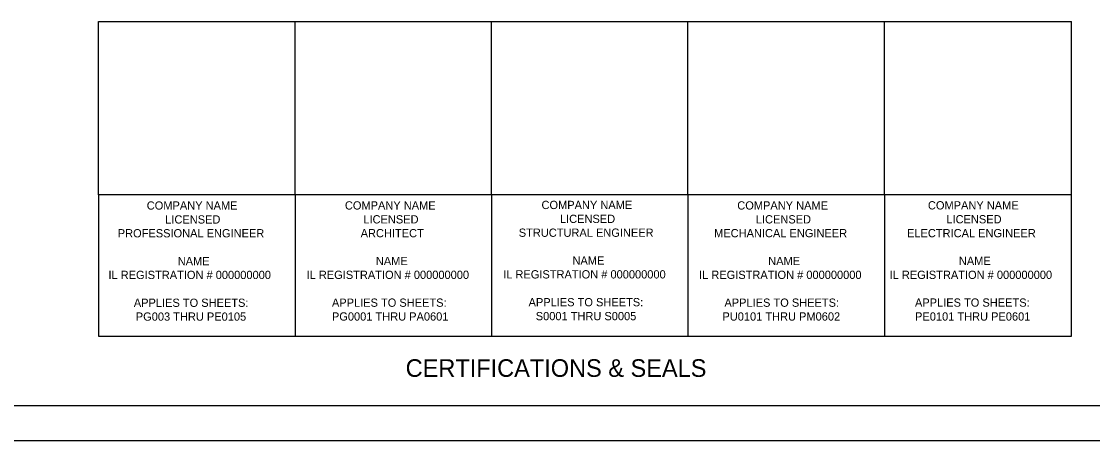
# Model space of a CAD drawing. Extents: x 46.6 to 90.4, y 0.3 to 22.3.
# Drawn here: x 58.96 to 70.28, y 0.26 to 4.69 of the extents above; entities that cross this region are included whole.
import ezdxf

# ---------------------------------------------------------------- set-up
doc = ezdxf.new("R2010")
doc.units = 0
doc.layers.add('Level 1', color=7, linetype='Continuous')

msp = doc.modelspace()

# ---------------------------------------------------------------- linework, layer by layer
at = {"layer": 'Level 1'}
for p, q in [((59.777, 2.855), (59.777, 4.688)), ((59.777, 4.688), (70.058, 4.688)), ((61.853, 2.855), (61.853, 4.688)), ((63.93, 2.855), (63.93, 4.688)), ((66.006, 2.855), (66.006, 4.688)), ((68.082, 2.855), (68.082, 4.688)), ((70.058, 2.855), (70.058, 4.688)), ((70.058, 2.855), (59.777, 2.855)), ((59.777, 2.855), (59.777, 1.364)), ((61.853, 2.855), (61.853, 1.364)), ((63.93, 2.855), (63.93, 1.364)), ((66.006, 2.855), (66.006, 1.364)), ((68.082, 2.855), (68.082, 1.364)), ((70.058, 1.364), (70.058, 2.855)), ((59.777, 1.364), (70.058, 1.364)), ((80.019, 0.629), (47.876, 0.629)), ((46.583, 0.261), (80.605, 0.261))]:
    msp.add_line(p, q, dxfattribs=at)

# ---------------------------------------------------------------- texts
for s, height, p in [('COMPANY NAME', 0.08719, (60.286, 2.7)), ('COMPANY NAME', 0.08719, (62.38, 2.701)), ('COMPANY NAME', 0.08719, (64.458, 2.706)), ('COMPANY NAME', 0.08719, (66.527, 2.701)), ('COMPANY NAME', 0.08719, (68.542, 2.702)), ('LICENSED', 0.0872, (60.481, 2.553)), ('LICENSED', 0.0872, (62.575, 2.554)), ('LICENSED', 0.0872, (64.653, 2.559)), ('LICENSED', 0.0872, (66.723, 2.554)), ('LICENSED', 0.0872, (68.737, 2.555)), (' PROFESSIONAL ENGINEER', 0.08719, (59.947, 2.407)), (' ARCHITECT', 0.0872, (62.514, 2.408)), (' STRUCTURAL ENGINEER', 0.08719, (64.185, 2.413)), ('MECHANICAL ENGINEER', 0.08719, (66.282, 2.408)), ('ELECTRICAL ENGINEER', 0.08719, (68.321, 2.408)), ('NAME', 0.0872, (60.613, 2.113)), ('NAME', 0.0872, (62.707, 2.114)), ('NAME', 0.0872, (64.785, 2.119)), ('NAME', 0.0872, (66.854, 2.114)), ('NAME', 0.0872, (68.869, 2.115)), ('IL REGISTRATION # 000000000', 0.08719, (59.881, 1.967)), ('IL REGISTRATION # 000000000', 0.08719, (61.975, 1.968)), ('IL REGISTRATION # 000000000', 0.08719, (64.053, 1.973)), ('IL REGISTRATION # 000000000', 0.08719, (66.123, 1.968)), ('IL REGISTRATION # 000000000', 0.08719, (68.137, 1.968)), ('APPLIES TO SHEETS:', 0.08719, (60.149, 1.673)), ('APPLIES TO SHEETS:', 0.08719, (62.243, 1.674)), ('APPLIES TO SHEETS:', 0.08719, (64.321, 1.679)), ('APPLIES TO SHEETS:', 0.08719, (66.391, 1.674)), ('APPLIES TO SHEETS: ', 0.08719, (68.405, 1.675)), ('PG003 THRU PE0105', 0.08719, (60.17, 1.527)), ('PG0001 THRU PA0601', 0.08719, (62.243, 1.528)), ('S0001 THRU S0005', 0.08719, (64.397, 1.532)), ('PU0101 THRU PM0602', 0.08719, (66.37, 1.528)), ('PE0101 THRU PE0601', 0.08719, (68.406, 1.528)), ('CERTIFICATIONS & SEALS', 0.186, (63.022, 0.934))]:
    msp.add_text(s, height=height, dxfattribs=at).set_placement(p)

doc.saveas('drawing.dxf')
